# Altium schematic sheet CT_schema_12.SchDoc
size 146 x 119 mm
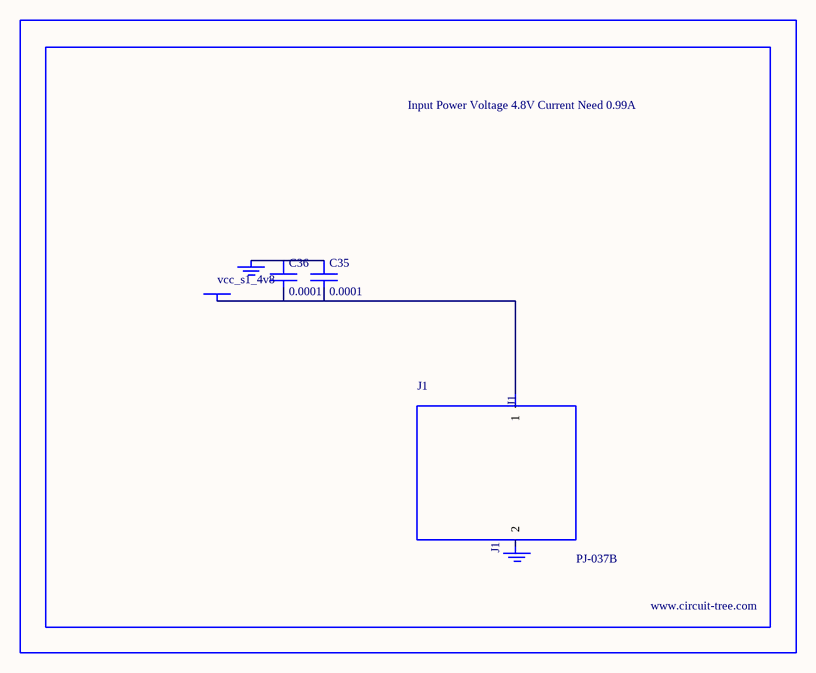
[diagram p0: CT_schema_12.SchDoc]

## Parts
BORDER11  (no value)
C35  0.0001  [EXV-9H]
C36  0.0001  [EXV-9H]
GND_INSTANCE_11_0  (no value)
GND_INSTANCE_11_1  (no value)
J1  PJ-037B  [PJ-037B_PACKAGE]
POWER_INSTANCE_11_0  vcc_s1_4v8

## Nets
NetC35_1: C35.1 C36.1 GND_INSTANCE_11_0.0(GND)
NetC35_2: C35.2 C36.2 J1.1 POWER_INSTANCE_11_0.0(PWR)

Not connected (* = marked no-connect by the designer): GND_INSTANCE_11_1 0(GND); J1 2

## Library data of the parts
BORDER11 = BORDER_PAGE11
C35 C36 = EDK107M035A9HAA
GND_INSTANCE_11_0 GND_INSTANCE_11_1 = GND
POWER_INSTANCE_11_0 = PWR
